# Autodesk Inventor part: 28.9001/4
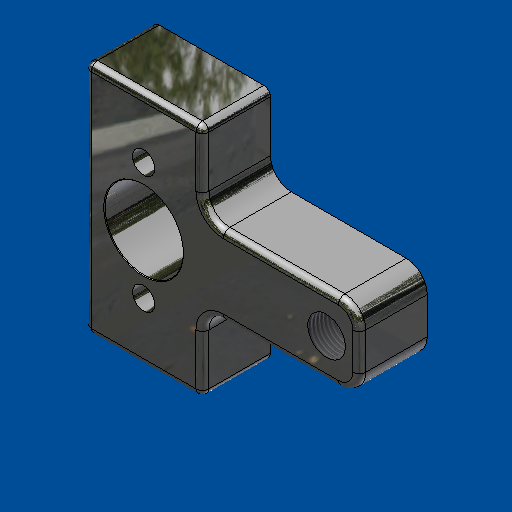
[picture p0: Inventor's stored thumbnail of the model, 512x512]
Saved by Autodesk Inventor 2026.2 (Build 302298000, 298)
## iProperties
Created: 2022-07
Part Number: 28.9001/4
Material: Aluminum 6061
Document SubType Name: Modeling
Designer: amoles
Density: 2.7 g/cm^3
Appearance: Anodized - Light Gray
Stock Number: 20.9478 1.25" X 4" AL BSTOCK
Description: \ROTATIONAL ELEMENT BEARING PLATE
Mass: 211.255 g
Surface Area: 173.148 cm^2
Volume: 78.2426 cm^3
Vendor: F
FINISH: ETCH & CLEAR ANODIZE
Author: amoles
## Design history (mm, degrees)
sketch "Sketch1"
  geometry: L1 (-22.5, 45)-(22.5, 45); L2 (22.5, 45)-(22.5, -45); L3 (22.5, -45)-(-22.5, -45); L4 (-22.5, -45)-(-22.5, 45); 3 further points
  constraints: 8 end point, 2 midpoint, 2 parallel, 1 horizontal, 1 horizontal alignment, 1 perpendicular, 1 vertical alignment
  dimensions: "d0" = 45 distance of L1.start L1.end; "d1" = 90 distance of L3.end L1.start
extrude "Extrusion1" new body sketch "Sketch1" distance "d2" = 26; taper "d3" = 0 deg
sketch "Sketch2"
  geometry: C1 r 12 at (0, 0); 1 further point
  constraints: 1 centre point, 1 coincident
  dimensions: "d4" = 24 diameter of C1
extrude "Extrusion2" cut sketch "Sketch2" extent not by distance; stored distance "d5" = 0; taper "d6" = 0 deg
sketch "Sketch3"
  geometry: C1 r 12 at (0, 0) reference; C2 r 12 at (0, 0) reference; C3 r 15 at (0, 0)
  constraints: 1 centre point, 1 coincident
  dimensions: "d7" = 30 diameter of C3
extrude "Extrusion3" cut sketch "Sketch3" distance "d8" = 22.825; taper "d9" = 0 deg
sketch "Sketch4"
  geometry: C1 r 12 at (0, 0) reference; 2 further points
  constraints: 2 vertical alignment
  dimensions: "d28" = 22.5 distance of point (0, 22.5) C1.centre; "d29" = 22.5 distance of point (0, -22.5) C1.centre
hole "Hole1" sketch "Sketch4" diameter "d12" = 8.5; stored, may be unused: countersink angle "d16" = 82 deg, drill point angle "d18" = 118 deg; dims "d13" = 19.05, "d14" = 13, "d15" = 5.5, "d17" = 25.4
fillet "Fillet1" dims "d37" = 2.4892
chamfer "Chamfer4" distance "d46" = 0.254; stored, may be unused: second distance "d47" = 3.175, angle "d48" = 45 deg
sketch "Sketch7"
  geometry: L1 (22.5, -42.511)-(22.5, 42.511) reference; L2 (-22.5, 42.511)-(-22.5, -42.511) reference; L3 (22.5, 15)-(82.5, 15); L4 (82.5, 15)-(82.5, -15); L5 (82.5, -15)-(22.5, -15); L6 (22.5, -15)-(22.5, 15); C1 r 15.254 at (0, 0) reference; 1 further point
  constraints: 8 end point, 2 parallel, 1 horizontal, 1 perpendicular, 1 point on line
  dimensions: "d49" = 30 distance of L3.end L4.end; "d50" = 105 distance between parallel lines of L4 L2; "d51" = 15 distance from line of L3 C1.centre (= 0.5 x d49)
extrude "Extrusion5" join sketch "Sketch7" distance "d52" = 26; taper "d53" = 0 deg
sketch "Sketch9"
  geometry: L1 (82.5, -15)-(82.5, 15) reference; C1 r 15.254 at (0, 0) reference; 2 further points
  constraints: 1 horizontal alignment, 1 midpoint
  dimensions: "d54" = 70 distance of point (70, 0) C1.centre
hole "Hole3" sketch "Sketch9" at (70, 0) diameter "d55" = 14.376; stored, may be unused: countersink angle "d59" = 82 deg, drill point angle "d61" = 118 deg; dims "d56" = 32.004, "d57" = 9.525, "d58" = 6.35, "d60" = 25.4
fillet "Fillet5" dims "d62" = 8
fillet "Fillet6" dims "d63" = 2.5
body "Solid1"
